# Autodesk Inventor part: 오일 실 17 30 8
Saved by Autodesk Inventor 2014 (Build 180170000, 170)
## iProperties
Created: 2026-06
Part Number: 오일 실 17 30 8
Material: 일반
Document SubType Name: Modeling
Designer: dg
Density: 1 g/cm^3
Appearance: 기본값
Author: dg
Author: jhkim
Description: 오일-실
Creation Date: 2026-05-29
Sending System: Autodesk Inventor 2027
Preprocessor: ST-DEVELOPER v20.1
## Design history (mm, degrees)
node "오일 실 17 30 81"
body "Solid1"
node "기준1"
